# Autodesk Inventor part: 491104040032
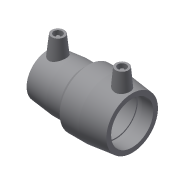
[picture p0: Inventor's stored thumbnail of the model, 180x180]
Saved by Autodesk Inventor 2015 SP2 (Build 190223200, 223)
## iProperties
Created: 2017-06
Part Number: 491104040032
Material: Generic
Description: PLASSON REDUCING COUPLER 40-32
Document SubType Name: Modeling
Designer: KIM
Mass: 54.8237 g
Surface Area: 155.252 cm^2
Volume: 54.8237 cm^3
Density: 1 g/cm^3
Appearance: Default
Author: KIM
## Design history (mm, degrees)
derived "491104.ipt"
feature "Solid1::491104.ipt"
tag "TaggingFeature1"
body "Solid1"
other parameters: "d2" = 44, "d4" = 24, "d5" = 39.6, "d7" = 32, "d8" = 168 deg, "d10" = 16, "d11" = 5.33333, "d14" = 17.6296, "d18" = 32, "d19" = 2, "d20" = 168 deg, "d22" = 108.92847, "d25" = 135 deg, "d29" = 43, "d30" = 15, "d31" = 31.5, "d34" = 6 deg, "d35" = 15, "d38" = 25.4, "d39" = 5 deg, "d41" = 4, "d42" = 14, "d43" = 0, "d45" = 4, "d46" = 14, "d47" = 0, "d48" = 44, "d50" = 56, "d52" = 28.8, "d53" = 17.6, "d54" = 5.86667, "d55" = 168 deg, "d56" = 26.4, "d57" = 44, "d58" = 50.4, "d59" = 2, "d60" = 135 deg, "d61" = 47, "d62" = 15, "d64" = 4, "d66" = 5 deg, "d67" = 14, "d68" = 0, "d69" = 31.5, "d70" = 44, "d71" = 56, "d73" = 52.64, "d76" = 2, "d77" = 168 deg, "d79" = 2, "d80" = 44, "d81" = 28.8, "d82" = 41.36, "d83" = 120 deg, "d88" = 15, "d89" = 25, "d90" = 5 deg, "d92" = 4, "d93" = 14, "d94" = 0, "d95" = 3, "d96" = 0, "d97" = 3, "d98" = 0, "d99" = 11.6, "d100" = 2.9, "d101" = 40.1192, "d102" = 20 deg, "d103" = 12.76, "d104" = 3.19, "d105" = 51.0608, "d106" = 3.60705, "d107" = 3, "d108" = 0, "d109" = 3, "d110" = 0, "d_1" = 32, "D_1" = 44, "A_1" = 43, "d_2" = 12, "L_1" = 44, "A_" = 47, "D_" = 56
